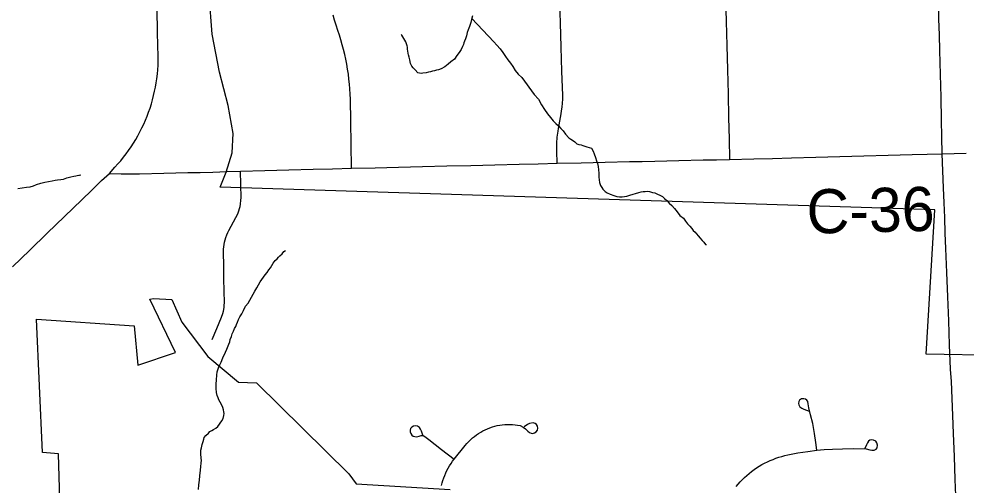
# Model space of a CAD drawing. Extents: x -11.4 to 84.1, y 11.1 to 59.
# Drawn here: x 27.387 to 28.606, y 42.377 to 42.977 of the extents above; entities that cross this region are included whole.
import ezdxf

# ---------------------------------------------------------------- set-up
doc = ezdxf.new("R2010")
doc.units = 0
for name, color, linetype in [('GM_X_City_Street', 7, 'Continuous'), ('GM_X_Corporation', 7, 'Continuous'), ('GM_X_County_Road_Text', 7, 'Continuous'), ('GM_X_Minor_River', 7, 'Continuous'), ('GM_X_State_Route', 7, 'Continuous'), ('GM_X_Township_Road', 7, 'Continuous')]:
    doc.layers.add(name, color=color, linetype=linetype)

msp = doc.modelspace()

# ---------------------------------------------------------------- linework, layer by layer
at = {"layer": 'GM_X_City_Street'}
for points in [[(28.4142, 42.4218), (28.413, 42.4319), (28.4112, 42.4435), (28.4091, 42.4563), (28.4062, 42.4674), (28.4039, 42.4766), (28.4032, 42.4817), (28.4025, 42.4845), (28.4014, 42.4864), (28.3997, 42.4876), (28.3973, 42.4881), (28.3946, 42.488), (28.3918, 42.4863), (28.3908, 42.4844), (28.3906, 42.4822), (28.3912, 42.4803), (28.3924, 42.4779), (28.3948, 42.4761), (28.3976, 42.4747), (28.4041, 42.4721)], [(27.9308, 42.3763), (27.9317, 42.3797), (27.9326, 42.383), (27.9337, 42.3863), (27.935, 42.3895), (27.9363, 42.3927), (27.9379, 42.3958), (27.9395, 42.3988), (27.9412, 42.4018), (27.9431, 42.4047), (27.9451, 42.4076), (27.9472, 42.4103), (27.9615, 42.4281), (27.9636, 42.4306), (27.9659, 42.4331), (27.9682, 42.4354), (27.9706, 42.4376), (27.9732, 42.4397), (27.9758, 42.4416), (27.9785, 42.4435), (27.9813, 42.4452), (27.9842, 42.4468), (27.9871, 42.4483), (27.9901, 42.4496), (27.9932, 42.4508), (27.9963, 42.4518), (27.9995, 42.4528), (28.0027, 42.4535), (28.0059, 42.4541), (28.0091, 42.4546), (28.0124, 42.4549), (28.0157, 42.4551), (28.0222, 42.4549), (28.0255, 42.4547), (28.0288, 42.4542), (28.032, 42.4537), (28.0362, 42.4517), (28.0392, 42.4495), (28.042, 42.4464), (28.0442, 42.4446), (28.0461, 42.4437), (28.0482, 42.4434), (28.0507, 42.4442), (28.0528, 42.4455), (28.0544, 42.4476), (28.055, 42.4501), (28.0544, 42.4528), (28.0532, 42.455), (28.0513, 42.4564), (28.0489, 42.4571), (28.044, 42.4564), (28.0415, 42.4549), (28.0371, 42.452)], [(27.9067, 42.4413), (27.9049, 42.4466), (27.9038, 42.4491), (27.9023, 42.4513), (27.9, 42.4529), (27.8968, 42.4532), (27.8946, 42.4527), (27.8927, 42.4516), (27.8911, 42.4497), (27.8904, 42.4478), (27.8905, 42.4455), (27.8913, 42.4433), (27.8926, 42.4413), (27.8945, 42.44), (27.8967, 42.4394), (27.8989, 42.4392), (27.9021, 42.4401), (27.9048, 42.4407), (27.9071, 42.4406), (27.9095, 42.4394), (27.9146, 42.4357), (27.9309, 42.423), (27.9472, 42.4103)], [(28.3105, 42.375), (28.313, 42.3781), (28.3156, 42.3811), (28.3184, 42.384), (28.3212, 42.3867), (28.3241, 42.3894), (28.3272, 42.392), (28.3302, 42.3945), (28.3334, 42.3969), (28.3367, 42.3991), (28.3401, 42.4013), (28.3435, 42.4033), (28.3469, 42.4052), (28.3505, 42.407), (28.3541, 42.4086), (28.3578, 42.4101), (28.3615, 42.4115), (28.3652, 42.4128), (28.3691, 42.4139), (28.3729, 42.4149), (28.3767, 42.4158), (28.3832, 42.4171), (28.3898, 42.4183), (28.3963, 42.4193), (28.4028, 42.4202), (28.4142, 42.4218), (28.4237, 42.4228), (28.4343, 42.4234), (28.4473, 42.4237), (28.4615, 42.4239), (28.4778, 42.4235), (28.4825, 42.4224), (28.4851, 42.4219), (28.488, 42.4221), (28.4906, 42.4234), (28.4917, 42.425), (28.4923, 42.4282), (28.4914, 42.4314), (28.49, 42.4335), (28.4873, 42.435), (28.4848, 42.4353), (28.4825, 42.4347), (28.4807, 42.4335), (28.4793, 42.4315), (28.4782, 42.4286), (28.476, 42.4242)]]:
    msp.add_lwpolyline(points, dxfattribs=at)
at = {"layer": 'GM_X_Corporation'}
for points in [[(28.6481, 42.5439), (28.5549, 42.5456), (28.5662, 42.7314), (27.6459, 42.7604), (27.6535, 42.7797), (27.6612, 42.8048), (27.6624, 42.8295), (27.6563, 42.8656), (27.6449, 42.9085), (27.6354, 42.9575), (27.6316, 43.0084)], [(27.4398, 42.3438), (27.4377, 42.4172), (27.4172, 42.419), (27.4093, 42.5906), (27.5351, 42.5819), (27.5396, 42.5315), (27.5882, 42.5476), (27.5553, 42.6165), (27.5599, 42.617), (27.5835, 42.616), (27.5966, 42.5866)], [(27.5966, 42.5866), (27.63, 42.5423), (27.6693, 42.5093), (27.6928, 42.5086), (27.8115, 42.3913), (27.8208, 42.3784), (27.9422, 42.3712)]]:
    msp.add_lwpolyline(points, dxfattribs=at)
at = {"layer": 'GM_X_Minor_River'}
for points in [[(27.9709, 42.9811), (27.9695, 42.9762), (27.9684, 42.9723), (27.9677, 42.9701), (27.967, 42.9674), (27.9652, 42.9632), (27.9641, 42.9597), (27.963, 42.9555), (27.9616, 42.9513), (27.9605, 42.9483), (27.9598, 42.9464), (27.959, 42.9441), (27.9579, 42.9418), (27.9561, 42.9379), (27.9535, 42.9337), (27.9505, 42.9298), (27.9476, 42.9252), (27.9427, 42.9217), (27.9393, 42.919), (27.9352, 42.9155), (27.9303, 42.9128), (27.9269, 42.9116), (27.9246, 42.9112), (27.922, 42.9104), (27.9193, 42.9099), (27.9167, 42.9091), (27.9141, 42.9087), (27.911, 42.9079), (27.9069, 42.9071), (27.905, 42.907), (27.9027, 42.9074), (27.9004, 42.9077), (27.8969, 42.9115), (27.8942, 42.9141), (27.8927, 42.9164), (27.8911, 42.9197), (27.8899, 42.9243), (27.889, 42.9277), (27.8882, 42.9307), (27.8878, 42.9326), (27.8874, 42.936), (27.887, 42.9379), (27.8869, 42.9406), (27.8865, 42.9425), (27.8857, 42.9451), (27.8849, 42.9478), (27.8798, 42.9561), (27.8787, 42.9572)], [(27.9699, 42.9777), (27.9981, 42.9474), (28.0023, 42.9432), (28.0066, 42.9388), (28.0097, 42.9339), (28.0132, 42.9286), (28.0163, 42.9245), (28.0198, 42.9203), (28.0226, 42.9158), (28.0257, 42.9109), (28.0296, 42.9061), (28.0342, 42.9016), (28.0501, 42.8798), (28.0556, 42.8738), (28.0595, 42.8666), (28.0634, 42.8606), (28.0673, 42.855), (28.0711, 42.8501), (28.0746, 42.846), (28.0781, 42.8426), (28.0816, 42.8396), (28.0847, 42.8362), (28.0874, 42.8329), (28.0905, 42.8287), (28.0947, 42.8242), (28.0974, 42.8224), (28.0997, 42.8209), (28.1024, 42.8187), (28.1051, 42.8164), (28.1078, 42.8153), (28.1109, 42.815), (28.1128, 42.8143), (28.1154, 42.8135), (28.1181, 42.8125), (28.1208, 42.8114), (28.1238, 42.8106), (28.1262, 42.8069), (28.1274, 42.8035), (28.129, 42.7986), (28.1306, 42.7944), (28.1318, 42.791), (28.1326, 42.7872), (28.133, 42.783), (28.1335, 42.7785), (28.1336, 42.7732), (28.1345, 42.7667), (28.1357, 42.7626), (28.1372, 42.7599), (28.1384, 42.758), (28.1415, 42.755), (28.1442, 42.7532), (28.148, 42.7513), (28.1526, 42.7499), (28.1568, 42.7484), (28.1602, 42.7481), (28.1633, 42.7482), (28.1663, 42.7486), (28.1693, 42.749), (28.1735, 42.7502), (28.1848, 42.7535), (28.1878, 42.7543), (28.1905, 42.7551), (28.1931, 42.7551), (28.1958, 42.7552), (28.1988, 42.7548), (28.2027, 42.7538), (28.2057, 42.7531), (28.2088, 42.7516), (28.2118, 42.7501), (28.2153, 42.7483), (28.218, 42.746), (28.2211, 42.7434), (28.2242, 42.7401), (28.2273, 42.7367), (28.2307, 42.7329), (28.2342, 42.7288), (28.2377, 42.7239), (28.2423, 42.7206), (28.2451, 42.7168), (28.2478, 42.7134), (28.2505, 42.7104), (28.2532, 42.7074), (28.2551, 42.7048), (28.2575, 42.7026), (28.259, 42.7007), (28.2617, 42.6973), (28.2637, 42.6951), (28.2664, 42.6917), (28.2687, 42.6895), (28.271, 42.6868), (28.2722, 42.6865)], [(27.3852, 42.759), (27.3909, 42.7598), (27.3962, 42.7603), (27.4011, 42.7611), (27.4053, 42.7623), (27.4094, 42.7639), (27.4147, 42.7655), (27.42, 42.7668), (27.4249, 42.768), (27.4295, 42.7688), (27.4333, 42.7696), (27.4363, 42.7701), (27.4405, 42.7705), (27.4439, 42.7709), (27.4484, 42.7725), (27.4533, 42.7738), (27.4575, 42.7746), (27.4598, 42.775), (27.4616, 42.7754), (27.4639, 42.7758), (27.4647, 42.7759), (27.4662, 42.7763)], [(27.6181, 42.3712), (27.6184, 42.3772), (27.6191, 42.3833), (27.6197, 42.389), (27.6204, 42.3963), (27.621, 42.4009), (27.6213, 42.405), (27.6217, 42.4089), (27.6212, 42.4111), (27.6212, 42.413), (27.6208, 42.4161), (27.6207, 42.4195), (27.6211, 42.4218), (27.6218, 42.4248), (27.6228, 42.4294), (27.6239, 42.4332), (27.6246, 42.4359), (27.6253, 42.4382), (27.6272, 42.4409), (27.6306, 42.444), (27.6324, 42.4459), (27.6351, 42.4471), (27.6373, 42.4487), (27.6403, 42.4502), (27.6426, 42.4525), (27.6481, 42.4599), (27.6496, 42.4629), (27.6507, 42.4664), (27.651, 42.469), (27.6506, 42.4713), (27.6502, 42.474), (27.6494, 42.477), (27.6474, 42.4808), (27.6458, 42.4838), (27.6443, 42.4868), (27.6431, 42.4891), (27.6419, 42.4921), (27.6411, 42.4962), (27.6406, 42.5012), (27.6405, 42.5069), (27.6412, 42.5126), (27.6415, 42.5183), (27.6421, 42.5229), (27.6436, 42.5278), (27.6454, 42.5317), (27.6473, 42.5351), (27.6494, 42.5409), (27.6527, 42.5481), (27.6542, 42.552), (27.6571, 42.5585), (27.6582, 42.5615), (27.6589, 42.5646), (27.6604, 42.5684), (27.6614, 42.5719), (27.6629, 42.5753), (27.6644, 42.5784), (27.6659, 42.5811), (27.6669, 42.5837), (27.668, 42.5868), (27.6695, 42.5902), (27.6713, 42.5937), (27.6736, 42.5975), (27.6758, 42.6018), (27.6783, 42.6071), (27.6817, 42.611), (27.6839, 42.6152), (27.6861, 42.6187), (27.6883, 42.6229), (27.6905, 42.6267), (27.6931, 42.6309), (27.6953, 42.6348), (27.6975, 42.6386), (27.7039, 42.6475), (27.7065, 42.6505), (27.7083, 42.654), (27.7105, 42.6567), (27.7124, 42.6598), (27.7142, 42.6628), (27.7168, 42.6659), (27.7191, 42.6682), (27.7209, 42.6702), (27.7228, 42.6721), (27.7258, 42.6748), (27.7277, 42.6775), (27.7299, 42.6791)]]:
    msp.add_lwpolyline(points, dxfattribs=at)
at = {"layer": 'GM_X_State_Route'}
for points in [[(28.5864, 42.5264), (28.5852, 42.5575), (28.584, 42.5885), (28.5828, 42.6195), (28.5816, 42.6506), (28.5804, 42.6816), (28.5796, 42.7015), (28.5789, 42.7214), (28.5782, 42.7404), (28.5775, 42.7595), (28.5765, 42.7815), (28.5756, 42.8036), (28.5752, 42.8253), (28.5747, 42.8469), (28.5741, 42.8762), (28.5734, 42.9054), (28.5726, 42.9364), (28.572, 42.9566), (28.5714, 42.9768), (28.5708, 43.0032)], [(28.5935, 42.3532), (28.5924, 42.3843), (28.5913, 42.4138), (28.5903, 42.4433), (28.5892, 42.4666), (28.5883, 42.4886), (28.5874, 42.5105), (28.5864, 42.5264)]]:
    msp.add_lwpolyline(points, dxfattribs=at)
at = {"layer": 'GM_X_Township_Road'}
for points in [[(28.0796, 42.7913), (28.0793, 42.807), (28.0794, 42.8173), (28.0795, 42.8199), (28.0797, 42.8224), (28.08, 42.825), (28.0802, 42.8275), (28.0806, 42.8301), (28.081, 42.8326), (28.0815, 42.836), (28.0848, 42.8548), (28.0854, 42.8587), (28.0861, 42.8637), (28.0866, 42.8687), (28.0869, 42.8737), (28.087, 42.8787), (28.086, 42.9098), (28.085, 42.9408), (28.0841, 42.9719), (28.0832, 42.9978)], [(28.2967, 43.0048), (28.2975, 42.9738), (28.2982, 42.9427), (28.299, 42.9117), (28.2998, 42.8806), (28.3005, 42.8496), (28.3012, 42.8229), (28.3019, 42.7963)], [(27.5031, 42.778), (27.5103, 42.7863), (27.5141, 42.7904), (27.5177, 42.7946), (27.5212, 42.799), (27.5246, 42.8034), (27.5278, 42.8079), (27.531, 42.8125), (27.5341, 42.8172), (27.537, 42.8219), (27.5397, 42.8268), (27.5424, 42.8317), (27.5449, 42.8367), (27.5473, 42.8417), (27.5496, 42.8468), (27.5517, 42.8519), (27.5536, 42.8572), (27.5555, 42.8624), (27.5572, 42.8677), (27.5588, 42.8731), (27.5601, 42.8785), (27.5614, 42.8839), (27.5626, 42.8894), (27.5636, 42.8949), (27.5641, 42.9001), (27.565, 42.9063), (27.5654, 42.9117), (27.5658, 42.9174), (27.5661, 42.9235), (27.566, 42.9283), (27.5652, 42.9594), (27.5645, 42.9905)], [(27.8151, 42.7848), (27.8146, 42.8158), (27.814, 42.8449), (27.8135, 42.874), (27.8133, 42.8804), (27.8129, 42.8869), (27.8124, 42.8933), (27.8117, 42.8997), (27.8109, 42.9061), (27.81, 42.9125), (27.8089, 42.9188), (27.8077, 42.9251), (27.8063, 42.9314), (27.8048, 42.9377), (27.8031, 42.9439), (27.8014, 42.9501), (27.7994, 42.9563), (27.7974, 42.9624), (27.7951, 42.9689), (27.7931, 42.9755), (27.7912, 42.9821)], [(27.5031, 42.778), (27.5185, 42.7777), (27.542, 42.7778), (27.5731, 42.7785), (27.6041, 42.7792), (27.6201, 42.7796), (27.6362, 42.78), (27.6542, 42.7805), (27.6722, 42.7811), (27.7033, 42.7819), (27.7344, 42.7827), (27.7654, 42.7835), (27.7903, 42.7841), (27.8151, 42.7848), (27.8453, 42.7855), (27.8754, 42.7862), (27.9065, 42.787), (27.9376, 42.7878), (27.9686, 42.7885), (27.9997, 42.7893), (28.0307, 42.7901), (28.0552, 42.7907), (28.0796, 42.7913), (28.1107, 42.792), (28.1417, 42.7927), (28.1728, 42.7934), (28.1892, 42.7937), (28.2055, 42.7941), (28.2366, 42.7948), (28.2677, 42.7955), (28.2848, 42.7959), (28.3019, 42.7963), (28.3329, 42.797), (28.3573, 42.7975), (28.3817, 42.7981), (28.4128, 42.799), (28.4439, 42.7999), (28.4749, 42.8007), (28.506, 42.8016), (28.537, 42.8025), (28.5563, 42.803), (28.5756, 42.8036), (28.6065, 42.8043)], [(27.3785, 42.6579), (27.4008, 42.6795), (27.4231, 42.7012), (27.4454, 42.7228), (27.4678, 42.7444), (27.4805, 42.7567), (27.4931, 42.769), (27.5031, 42.778)], [(27.6357, 42.5643), (27.6416, 42.5787), (27.6475, 42.5931), (27.6491, 42.5978), (27.6499, 42.6007), (27.6508, 42.6056), (27.6511, 42.6085), (27.6513, 42.6115), (27.6507, 42.6426), (27.6504, 42.6596), (27.6501, 42.6766), (27.6502, 42.6809), (27.6505, 42.6839), (27.6509, 42.6869), (27.6515, 42.6898), (27.6522, 42.6927), (27.653, 42.6955), (27.6544, 42.6992), (27.6557, 42.702), (27.657, 42.7046), (27.666, 42.7213), (27.6676, 42.7246), (27.6688, 42.7273), (27.6698, 42.7301), (27.6707, 42.7329), (27.6714, 42.7358), (27.672, 42.7387), (27.6726, 42.7437), (27.6728, 42.7466), (27.6725, 42.7639), (27.6722, 42.7811)]]:
    msp.add_lwpolyline(points, dxfattribs=at)

# ---------------------------------------------------------------- texts
at = {"layer": 'GM_X_County_Road_Text'}
msp.add_text('C-36', height=0.05682, rotation=1.3726, dxfattribs=at).set_placement((28.4017, 42.7005))

doc.saveas('drawing.dxf')
